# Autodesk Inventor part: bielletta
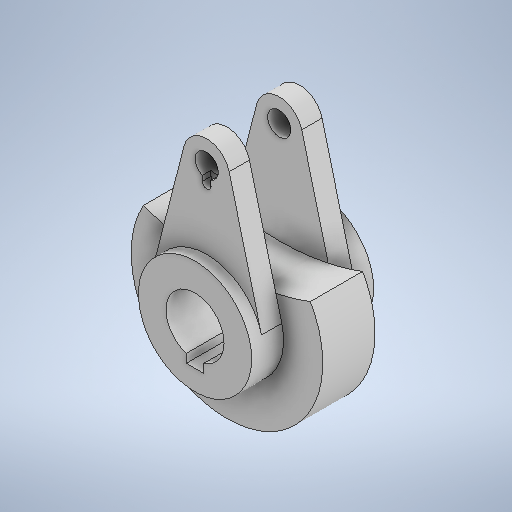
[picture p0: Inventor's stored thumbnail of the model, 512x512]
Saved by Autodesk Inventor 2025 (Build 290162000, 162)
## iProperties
Created: 2025-10
Part Number: bielletta
Material: Generico
Document SubType Name: Modeling
Designer: 18619647
Density: 1 g/cm^3
Appearance: Default
Author: 18619647
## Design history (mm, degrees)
sketch "Schizzo1"
  geometry: C1 r 33 at (0, 0); 1 further point
  constraints: 1 centre point, 1 coincident
  dimensions: "d0" = 66 diameter of C1
extrude "Estrusione1" new body sketch "Schizzo1" distance "d1" = 18; taper "d2" = 0 deg
sketch "Schizzo2"
  geometry: L1 (-7.746, 48)-(-18.881, 4.875); L2 (7.746, 48)-(18.881, 4.875); A1 r 19.5 centre (0, 0) between (-18.881, 4.875) and (18.881, 4.875); A2 r 8 centre (0, 46) between (7.746, 48) and (-7.746, 48); 1 further point
  constraints: 4 end point, 4 point on circle, 2 centre point, 2 tangent, 1 coincident
  dimensions: "d3" = 39 diameter of A1; "d5" = 16 diameter of A2
extrude "Estrusione2" join sketch "Schizzo2" distance "d6" = 7; taper "d8" = 0 deg; dims "d7" = 25, "d9" = 0
sketch "Schizzo3"
  geometry: C1 r 19.5 at (0, 0); 1 further point
  constraints: 1 centre point, 1 coincident
extrude "Estrusione3" join sketch "Schizzo3" distance "d10" = 4; taper "d12" = 0 deg; dims "d11" = 38, "d13" = 0
sketch "Schizzo4"
  geometry: C1 r 19.5 at (0, 0) reference; 2 further points
  constraints: 1 coincident
hole "Foro1" sketch "Schizzo4" at (0, 0) diameter "d14" = 20; stored, may be unused: countersink angle "d18" = 90 deg, drill point angle "d20" = 118 deg; dims "d15" = 6, "d16" = 4, "d17" = 2, "d19" = 8
node "Piano di lavoro1"
sketch "Schizzo5"
  geometry: C1 r 81 at (0, 92); 1 further point
  constraints: 1 centre point
  dimensions: "d23" = 162 diameter of C1
extrude "Estrusione4" cut sketch "Schizzo5" distance "d24" = 18; taper "d25" = 0 deg
sketch "Schizzo6"
  geometry: A1 r 8 centre (0, 46) between (7.746, 48) and (-7.746, 48) reference; 2 further points
  constraints: 1 coincident
hole "Foro2" sketch "Schizzo6" at (0, 46) diameter "d26" = 8; stored, may be unused: countersink angle "d30" = 90 deg, drill point angle "d32" = 118 deg; dims "d27" = 6, "d28" = 4, "d29" = 2, "d31" = 8
sketch "Schizzo7"
  geometry: L1 (0, -12.5)-(-3, -12.5); L2 (-3, -12.5)-(-3, -6.5); L3 (-3, -6.5)-(3, -6.5); L4 (3, -6.5)-(3, -12.5); L5 (3, -12.5)-(0, -12.5); C1 r 10 at (0, 0) reference; 1 further point
  constraints: 10 end point, 2 perpendicular, 1 point on line
  dimensions: "d34" = 3 distance of L1.start L1.end; "d35" = 6 distance of L1.end L2.end; "d36" = 6 distance of L2.end L3.end
extrude "Estrusione5" cut sketch "Schizzo7" extent not by distance; stored distance "d37" = 0; taper "d38" = 0 deg
sketch "Schizzo8"
  geometry: L1 (-1.5, 40.5)-(-1.5, 43.736); L2 (-1.5, 43.736)-(1.5, 43.736); L3 (1.5, 43.736)-(1.5, 40.5); C1 r 4 at (0, 46) reference; A1 r 1.5 centre (0, 40.5) between (-1.5, 40.5) and (1.5, 40.5); 1 further point
  constraints: 6 end point, 2 point on circle, 2 tangent, 1 centre point, 1 perpendicular, 1 vertical
  dimensions: "d41" = 3 diameter of A1; "d42" = 3 distance of L1.end L2.end
extrude "Estrusione6" cut sketch "Schizzo8" distance "d43" = 3; taper "d44" = 0 deg
node "Solido1"
other parameters: "d21" = -7
